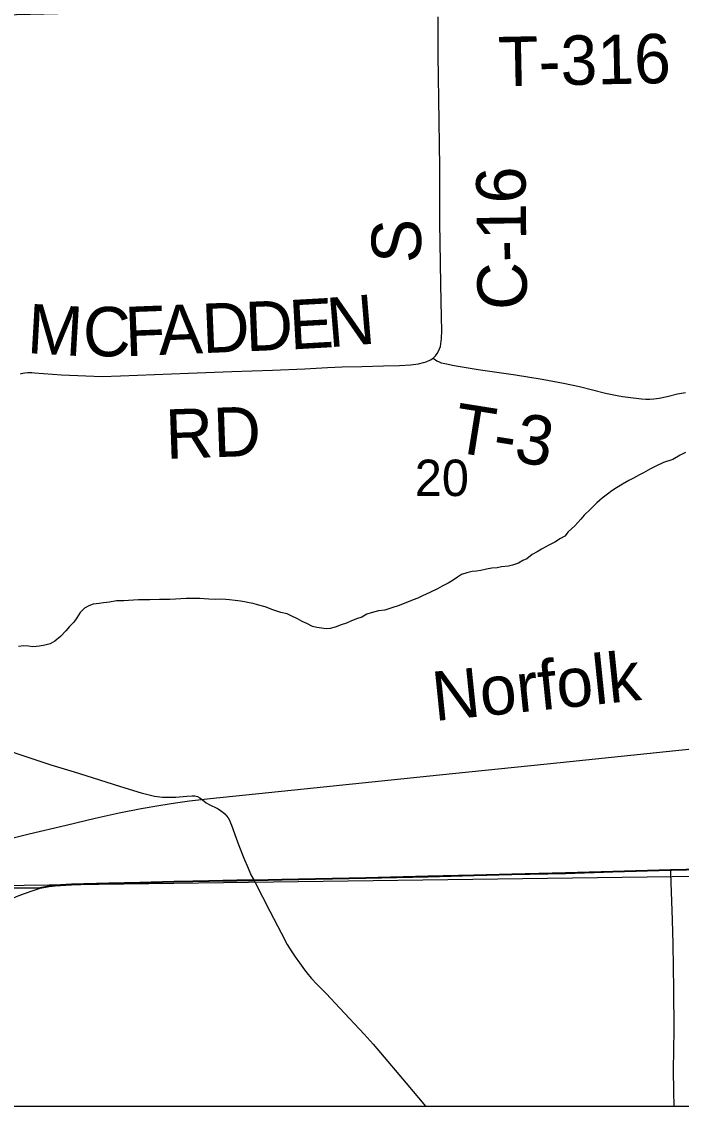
# Model space of a CAD drawing. Extents: x 0 to 34, y 0 to 22.
# Drawn here: x 4.5 to 5.258, y 14.1 to 15.347 of the extents above; entities that cross this region are included whole.
import ezdxf

# ---------------------------------------------------------------- set-up
doc = ezdxf.new("R2010")
doc.units = 0
for name, color, linetype in [('Default', 7, 'Continuous'), ('GM_X_County_Road', 7, 'Continuous'), ('GM_X_County_Road_Text', 7, 'Continuous'), ('GM_X_Minor_River', 7, 'Continuous'), ('GM_X_Rail_Line', 7, 'Continuous'), ('GM_X_Rail_Line_Text', 7, 'Continuous'), ('GM_X_Section', 7, 'Continuous'), ('GM_X_Section_Text', 7, 'Continuous'), ('GM_X_State_Route', 7, 'Continuous'), ('GM_X_Township_Road', 7, 'Continuous'), ('GM_X_Township_Road_Text', 7, 'Continuous'), ('SH_Cut_Line', 7, 'Continuous'), ('SH_Data', 7, 'Continuous')]:
    doc.layers.add(name, color=color, linetype=linetype)

msp = doc.modelspace()

# ---------------------------------------------------------------- linework, layer by layer
at = {"layer": 'Default'}
for points in [[(4.282, 14.3483), (4.5209, 14.3512), (4.5313, 14.353), (4.5384, 14.3539), (4.5444, 14.3544), (4.5572, 14.3551), (4.6001, 14.3564), (4.6358, 14.3573), (4.6748, 14.3583), (4.6965, 14.3587), (4.7151, 14.3591), (4.7472, 14.3597), (4.767, 14.36), (4.799, 14.3607), (4.8953, 14.3626), (4.9668, 14.3643), (5.0196, 14.3658), (5.0631, 14.3669), (5.1251, 14.3682), (5.1792, 14.3699), (5.2457, 14.3717), (5.2464, 14.3718), (5.3334, 14.3738)], [(5.3334, 14.3738), (5.2464, 14.3718), (5.2457, 14.3717), (5.1792, 14.3699), (5.1251, 14.3682), (5.0631, 14.3669), (5.0196, 14.3658), (4.9668, 14.3643), (4.8953, 14.3626), (4.799, 14.3607), (4.767, 14.36), (4.7472, 14.3597), (4.7151, 14.3591), (4.6965, 14.3587), (4.6748, 14.3583), (4.6358, 14.3573), (4.6001, 14.3564), (4.5572, 14.3551), (4.5444, 14.3544), (4.5384, 14.3539), (4.5313, 14.353), (4.5209, 14.3512), (4.282, 14.3483)], [(3.6803, 14.1), (8.9, 14.1)]]:
    msp.add_lwpolyline(points, dxfattribs=at)
at = {"layer": 'GM_X_County_Road'}
for points in [[(4.9727, 14.9598), (4.9754, 14.9625), (4.9775, 14.9651), (4.979, 14.9678), (4.9802, 14.9706), (4.9811, 14.9734), (4.9817, 14.9764), (4.9825, 14.9824), (4.9827, 14.9917), (4.9823, 15.0072), (4.982, 15.0259), (4.9817, 15.0445), (4.9812, 15.0693), (4.9807, 15.116), (4.9806, 15.1517), (4.9804, 15.1796), (4.9801, 15.206), (4.9798, 15.2318), (4.9786, 15.3085), (4.9786, 15.3399), (4.9786, 15.3521)], [(4.4986, 14.9418), (4.5013, 14.9425), (4.5037, 14.9429), (4.5072, 14.9433), (4.5115, 14.9433), (4.5146, 14.9432), (4.5457, 14.9409), (4.5737, 14.9394), (4.5923, 14.939), (4.6136, 14.9395), (4.6917, 14.9427), (4.7415, 14.9445), (4.7882, 14.9462), (4.8255, 14.9477), (4.8514, 14.9491), (4.8683, 14.9498), (4.8908, 14.9503), (4.9156, 14.9509), (4.9343, 14.9515), (4.9467, 14.9524), (4.9559, 14.9535), (4.9618, 14.9548), (4.9647, 14.9558), (4.9696, 14.9578), (4.9727, 14.9598)], [(4.7672, 14.3595), (4.7684, 14.3571), (4.7851, 14.3242), (4.7981, 14.2993), (4.8051, 14.2861), (4.8103, 14.2775), (4.8119, 14.2751), (4.8142, 14.2718), (4.8191, 14.2648), (4.825, 14.2568), (4.8291, 14.2516), (4.8331, 14.247), (4.8386, 14.2409), (4.8445, 14.2348), (4.8497, 14.2295), (4.8656, 14.2127), (4.8936, 14.1827), (4.9038, 14.1712), (4.9418, 14.1264), (4.964, 14.1)]]:
    msp.add_lwpolyline(points, dxfattribs=at)
at = {"layer": 'GM_X_Minor_River'}
for points in [[(5.2629, 14.8514), (5.2568, 14.8483), (5.2484, 14.8434), (5.2374, 14.84), (5.2286, 14.8358), (5.2225, 14.8328), (5.2145, 14.8282), (5.2099, 14.8259), (5.2031, 14.8221), (5.1977, 14.8191), (5.1905, 14.8149), (5.1836, 14.8107), (5.1783, 14.8073), (5.173, 14.8035), (5.1669, 14.799), (5.1608, 14.7936), (5.1535, 14.7864), (5.1463, 14.7796), (5.1425, 14.775), (5.1356, 14.767), (5.128, 14.7602), (5.1242, 14.7552), (5.1193, 14.7526), (5.1128, 14.7484), (5.1059, 14.745), (5.0972, 14.7404), (5.0922, 14.7374), (5.0865, 14.7344), (5.0804, 14.7294), (5.0758, 14.7275), (5.0709, 14.7241), (5.064, 14.7218), (5.0594, 14.7207), (5.0514, 14.7199), (5.0465, 14.7188), (5.0403, 14.7184), (5.0342, 14.7173), (5.0278, 14.7158), (5.0228, 14.715), (5.0178, 14.7146), (5.0117, 14.7131), (5.0056, 14.7112), (5.0007, 14.7082), (4.9957, 14.7048), (4.99, 14.7013), (4.9831, 14.6979), (4.9778, 14.6949), (4.969, 14.6907), (4.9607, 14.6869), (4.9553, 14.6842), (4.95, 14.682), (4.9454, 14.6801), (4.9385, 14.6774), (4.9336, 14.6755), (4.9252, 14.6729), (4.9172, 14.6702), (4.9099, 14.6694), (4.9016, 14.6672), (4.8966, 14.6656), (4.8909, 14.6622), (4.8848, 14.6603), (4.8783, 14.6577), (4.8733, 14.6554), (4.8672, 14.6535), (4.8604, 14.6508), (4.8543, 14.6493), (4.8497, 14.6486), (4.8447, 14.6497), (4.839, 14.6505), (4.834, 14.6516), (4.8275, 14.655), (4.8222, 14.6573), (4.8168, 14.6604), (4.8096, 14.6638), (4.805, 14.6661), (4.7977, 14.6676), (4.7886, 14.6706), (4.7798, 14.6741), (4.771, 14.6764), (4.766, 14.6779), (4.7615, 14.6786), (4.7561, 14.6798), (4.7515, 14.6806), (4.7454, 14.6813), (4.7389, 14.6821), (4.7344, 14.6825), (4.7275, 14.6829), (4.7229, 14.6825), (4.7149, 14.6829), (4.7096, 14.6832), (4.7046, 14.6836), (4.6889, 14.6836)], [(4.6889, 14.6836), (4.6767, 14.6829), (4.6702, 14.6825), (4.6634, 14.6825), (4.6584, 14.6825), (4.6474, 14.6821), (4.6344, 14.6821), (4.6283, 14.6818), (4.6229, 14.6814), (4.6172, 14.681), (4.6088, 14.681), (4.6008, 14.6795), (4.5939, 14.6787), (4.589, 14.678), (4.5821, 14.6772), (4.5771, 14.6753), (4.5722, 14.6727), (4.5672, 14.6677), (4.5634, 14.6616), (4.56, 14.6563), (4.5551, 14.6514), (4.5509, 14.6464), (4.5444, 14.64), (4.5379, 14.6347), (4.5326, 14.6316), (4.5265, 14.6301), (4.5204, 14.629), (4.5128, 14.6282), (4.5078, 14.629), (4.5021, 14.6294), (4.4964, 14.6286)]]:
    msp.add_lwpolyline(points, dxfattribs=at)
at = {"layer": 'GM_X_Rail_Line'}
msp.add_lwpolyline([(4.4779, 14.4056), (4.5085, 14.413), (4.5511, 14.4232), (4.5846, 14.4313), (4.6121, 14.4374), (4.6374, 14.4422), (4.6599, 14.4461), (4.6768, 14.4488), (4.6928, 14.451), (4.7164, 14.4536), (4.8246, 14.4648), (4.9803, 14.4809), (5.1189, 14.4952), (5.2996, 14.5138)], dxfattribs=at)
at = {"layer": 'GM_X_Section'}
msp.add_lwpolyline([(4.4621, 15.354), (5.3765, 15.3766), (5.4966, 15.3772), (5.5053, 14.3671), (4.4738, 14.3535)], close=True, dxfattribs=at)
at = {"layer": 'GM_X_State_Route'}
for points in [[(4.5211, 14.3506), (4.5315, 14.3525), (4.5386, 14.3533), (4.5446, 14.3539), (4.5574, 14.3546), (4.6003, 14.3559), (4.636, 14.3567), (4.675, 14.3578), (4.6967, 14.3582), (4.7153, 14.3586), (4.7474, 14.3591), (4.7672, 14.3595), (4.7992, 14.3601), (4.8955, 14.362), (4.967, 14.3638), (5.0198, 14.3653), (5.0633, 14.3663), (5.1253, 14.3676), (5.1795, 14.3693), (5.2459, 14.3712), (5.2466, 14.3712), (5.3336, 14.3733)], [(4.4736, 14.3326), (4.4796, 14.3346), (4.4941, 14.3411), (4.5033, 14.3446), (4.5131, 14.348), (4.5211, 14.3506)]]:
    msp.add_lwpolyline(points, dxfattribs=at)
at = {"layer": 'GM_X_Township_Road'}
for points in [[(4.9727, 14.9598), (4.977, 14.9569), (4.9797, 14.9557), (4.9821, 14.9547), (4.9844, 14.954), (4.988, 14.9532), (4.9971, 14.9513), (5.0246, 14.947), (5.0676, 14.9408), (5.0982, 14.9358), (5.1227, 14.9312), (5.1409, 14.9272), (5.171, 14.9198), (5.1843, 14.9168), (5.1905, 14.9157), (5.1966, 14.9149), (5.2123, 14.913), (5.2171, 14.9127), (5.2217, 14.9128), (5.2264, 14.9133), (5.2325, 14.9141), (5.2416, 14.916), (5.2536, 14.9189), (5.2627, 14.9205)], [(4.4775, 14.5111), (4.5069, 14.5011), (4.5335, 14.4925), (4.5602, 14.4843), (4.581, 14.4779), (4.6136, 14.4675), (4.6374, 14.4602), (4.6464, 14.4578), (4.6525, 14.4566), (4.6618, 14.4554), (4.6711, 14.4551), (4.6773, 14.4553), (4.6897, 14.4566), (4.6959, 14.457), (4.699, 14.4568), (4.7019, 14.456), (4.7047, 14.4545), (4.7095, 14.4506), (4.7121, 14.4489), (4.7148, 14.4473), (4.7259, 14.4417), (4.7285, 14.44), (4.731, 14.4382), (4.7333, 14.4362), (4.7354, 14.4339), (4.7372, 14.4314), (4.7388, 14.4287), (4.7401, 14.4259), (4.7412, 14.423), (4.7463, 14.4083), (4.7495, 14.3996), (4.7553, 14.3852), (4.7601, 14.3737), (4.763, 14.367), (4.7635, 14.3659), (4.7672, 14.3595)], [(5.2497, 14.1), (5.2496, 14.1168), (5.2492, 14.1418), (5.2497, 14.188), (5.2493, 14.2342), (5.2486, 14.2863), (5.2479, 14.3142), (5.2461, 14.3674), (5.2459, 14.3712)]]:
    msp.add_lwpolyline(points, dxfattribs=at)
at = {"layer": 'SH_Cut_Line'}
for points in [[(5.3334, 14.3738), (5.2464, 14.3718), (5.2457, 14.3717), (5.1792, 14.3699), (5.1251, 14.3682), (5.0631, 14.3669), (5.0196, 14.3658), (4.9668, 14.3643), (4.8953, 14.3626), (4.799, 14.3607), (4.767, 14.36), (4.7472, 14.3597), (4.7151, 14.3591), (4.6965, 14.3587), (4.6748, 14.3583), (4.6358, 14.3573), (4.6001, 14.3564), (4.5572, 14.3551), (4.5444, 14.3544), (4.5384, 14.3539), (4.5313, 14.353), (4.5209, 14.3512), (4.282, 14.3483)], [(4.282, 14.3483), (4.5209, 14.3512), (4.5313, 14.353), (4.5384, 14.3539), (4.5444, 14.3544), (4.5572, 14.3551), (4.6001, 14.3564), (4.6358, 14.3573), (4.6748, 14.3583), (4.6965, 14.3587), (4.7151, 14.3591), (4.7472, 14.3597), (4.767, 14.36), (4.799, 14.3607), (4.8953, 14.3626), (4.9668, 14.3643), (5.0196, 14.3658), (5.0631, 14.3669), (5.1251, 14.3682), (5.1792, 14.3699), (5.2457, 14.3717), (5.2464, 14.3718), (5.3334, 14.3738)], [(2.1, 14.1), (8.9, 14.1)]]:
    msp.add_lwpolyline(points, dxfattribs=at)
at = {"layer": 'SH_Data'}
msp.add_line((2.1, 14.1), (8.9, 14.1), dxfattribs=at)

# ---------------------------------------------------------------- texts
at = {"layer": 'GM_X_County_Road_Text'}
for s, height, rotation, p in [('C-16', 0.05682, 90.6725, (5.0808, 15.0157)), ('S', 0.0568, 90, (4.9589, 15.0692)), ('D', 0.0568, 2.4115, (4.7081, 14.9656)), ('D', 0.0568, 2.4369, (4.758, 14.9677)), ('E', 0.0568, 3.1927, (4.8088, 14.9698)), ('N', 0.0568, 4.7002, (4.8529, 14.9723)), ('M', 0.0568, 356.6768, (4.5054, 14.9658)), ('C', 0.0568, 359.7989, (4.5703, 14.9621)), ('F', 0.0568, 2.2215, (4.6196, 14.962)), ('A', 0.0568, 2.4049, (4.6581, 14.9635)), ('RD', 0.05682, 1.9774, (4.6661, 14.8441))]:
    msp.add_text(s, height=height, rotation=rotation, dxfattribs=at).set_placement(p)
at = {"layer": 'GM_X_Rail_Line_Text'}
msp.add_text('Norfolk', height=0.05663, rotation=5.8394, dxfattribs=at).set_placement((4.9746, 14.5427))
at = {"layer": 'GM_X_Section_Text'}
msp.add_text('20', height=0.04186, rotation=0, dxfattribs=at).set_placement((4.9517, 14.8014))
at = {"layer": 'GM_X_Township_Road_Text'}
for s, rotation, p in [('T-316', 1.1125, (5.048, 15.2723)), ('T-3', 350.9102, (4.9936, 14.8526))]:
    msp.add_text(s, height=0.05682, rotation=rotation, dxfattribs=at).set_placement(p)

doc.saveas('drawing.dxf')
